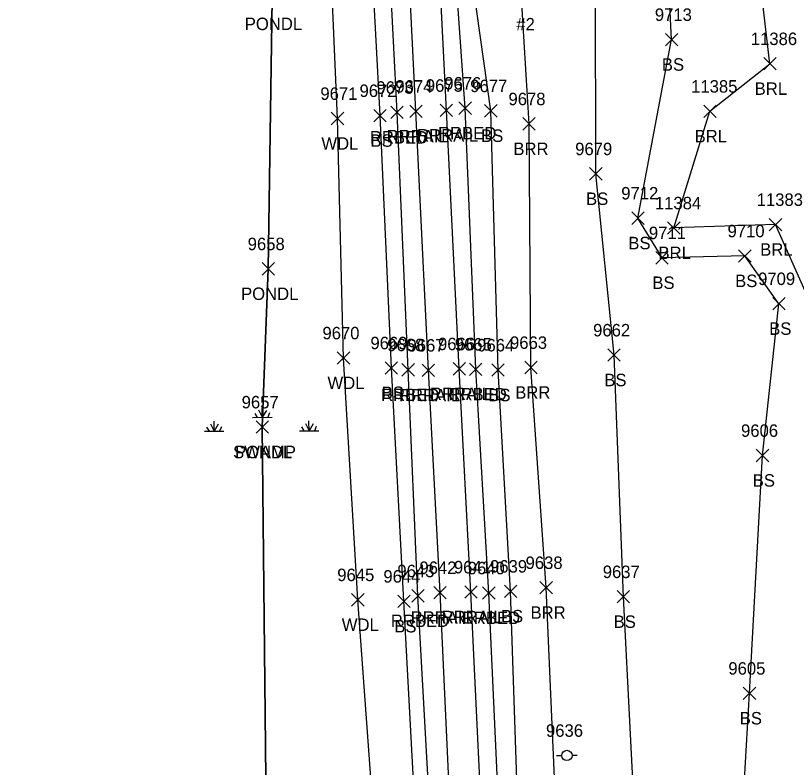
# Model space of a CAD drawing. Extents: x 1769141 to 1770911, y 735471 to 741449.
# Drawn here: x 1770166.6 to 1770292.1, y 739613.2 to 739733.9 of the extents above; entities that cross this region are included whole.
import ezdxf

# ---------------------------------------------------------------- set-up
doc = ezdxf.new("R2010")
doc.units = 0
for name, color, linetype in [('L_A', 7, 'Continuous'), ('L_I', 7, 'Continuous'), ('L_TIC', 7, 'Continuous'), ('LABL', 7, 'Continuous'), ('LAWA', 7, 'Continuous'), ('LAWE', 7, 'Continuous'), ('LELB', 7, 'Continuous'), ('LSOGP', 7, 'Continuous'), ('LWET', 7, 'Continuous'), ('R_A', 7, 'Continuous'), ('R_I', 7, 'Continuous'), ('R_TIC', 7, 'Continuous'), ('RR', 7, 'Continuous'), ('RRB', 7, 'Continuous'), ('U_C', 7, 'Continuous'), ('U_I', 7, 'Continuous'), ('UP', 7, 'Continuous')]:
    doc.layers.add(name, color=color, linetype=linetype)

msp = doc.modelspace()

# ---------------------------------------------------------------- linework, layer by layer
at = {"layer": 'L_TIC'}
for points in [[(1770271.01, 739729.06), (1770273.01, 739731.06)], [(1770273.01, 739729.06), (1770271.01, 739731.06)], [(1770286.82, 739725.18), (1770288.82, 739727.18)], [(1770288.82, 739725.18), (1770286.82, 739727.18)], [(1770241.96, 739717.62), (1770243.96, 739719.62)], [(1770243.96, 739717.62), (1770241.96, 739719.62)], [(1770277.17, 739717.54), (1770279.17, 739719.54)], [(1770279.17, 739717.54), (1770277.17, 739719.54)], [(1770217.32, 739716.38), (1770219.32, 739718.38)], [(1770219.32, 739716.38), (1770217.32, 739718.38)], [(1770224.17, 739716.84), (1770226.17, 739718.84)], [(1770226.17, 739716.84), (1770224.17, 739718.84)], [(1770248.1, 739715.52), (1770250.1, 739717.52)], [(1770250.1, 739715.52), (1770248.1, 739717.52)], [(1770258.83, 739707.5), (1770260.83, 739709.5)], [(1770260.83, 739707.5), (1770258.83, 739709.5)], [(1770265.61, 739700.38), (1770267.61, 739702.38)], [(1770267.61, 739700.38), (1770265.61, 739702.38)], [(1770271.36, 739698.8), (1770273.36, 739700.8)], [(1770273.36, 739698.8), (1770271.36, 739700.8)], [(1770287.7, 739699.35), (1770289.7, 739701.35)], [(1770289.7, 739699.35), (1770287.7, 739701.35)], [(1770269.48, 739694.01), (1770271.48, 739696.01)], [(1770271.48, 739694.01), (1770269.48, 739696.01)], [(1770282.78, 739694.31), (1770284.78, 739696.31)], [(1770284.78, 739694.31), (1770282.78, 739696.31)], [(1770206.21, 739692.24), (1770208.21, 739694.24)], [(1770208.21, 739692.24), (1770206.21, 739694.24)], [(1770288.25, 739686.64), (1770290.25, 739688.64)], [(1770290.25, 739686.64), (1770288.25, 739688.64)], [(1770261.76, 739678.39), (1770263.76, 739680.39)], [(1770263.76, 739678.39), (1770261.76, 739680.39)], [(1770218.3, 739677.92), (1770220.3, 739679.92)], [(1770220.3, 739677.92), (1770218.3, 739679.92)], [(1770225.99, 739676.33), (1770227.99, 739678.33)], [(1770227.99, 739676.33), (1770225.99, 739678.33)], [(1770243.13, 739675.98), (1770245.13, 739677.98)], [(1770245.13, 739675.98), (1770243.13, 739677.98)], [(1770248.41, 739676.39), (1770250.41, 739678.39)], [(1770250.41, 739676.39), (1770248.41, 739678.39)], [(1770205.24, 739666.83), (1770207.24, 739668.83)], [(1770207.24, 739666.83), (1770205.24, 739668.83)], [(1770285.61, 739662.26), (1770287.61, 739664.26)], [(1770287.61, 739662.26), (1770285.61, 739664.26)], [(1770245.15, 739640.46), (1770247.15, 739642.46)], [(1770247.15, 739640.46), (1770245.15, 739642.46)], [(1770250.86, 739641.04), (1770252.86, 739643.04)], [(1770252.86, 739641.04), (1770250.86, 739643.04)], [(1770263.26, 739639.58), (1770265.26, 739641.58)], [(1770265.26, 739639.58), (1770263.26, 739641.58)], [(1770220.6, 739639.09), (1770222.6, 739641.09)], [(1770222.6, 739639.09), (1770220.6, 739641.09)], [(1770228.01, 739638.85), (1770230.01, 739640.85)], [(1770230.01, 739638.85), (1770228.01, 739640.85)], [(1770283.52, 739624.07), (1770285.52, 739626.07)], [(1770285.52, 739624.07), (1770283.52, 739626.07)]]:
    msp.add_lwpolyline(points, dxfattribs=at)
at = {"layer": 'LABL'}
for points in [[(1770280.48, 739010.56), (1770278.67, 739061.29), (1770275.22, 739102.58), (1770273.98, 739143.9), (1770271.83, 739194.56), (1770272.18, 739226.41), (1770266.41, 739273.34), (1770265.32, 739313.93), (1770263.98, 739331.68), (1770262.51, 739367.87), (1770263.52, 739415.26), (1770260.53, 739460.74), (1770259.92, 739511.57), (1770256, 739547.93), (1770251.86, 739642.04), (1770249.41, 739677.39), (1770249.1, 739716.52), (1770247.5, 739742.9), (1770250.29, 739787.04), (1770239.75, 739833.98), (1770250.68, 739842.6), (1770271.28, 739846.58)], [(1770315.73, 739476.29), (1770304.71, 739488.57), (1770301.06, 739512.26), (1770299.15, 739548.11), (1770294.3, 739585.97), (1770295.34, 739626.16), (1770298.21, 739660.91), (1770301.72, 739669.63), (1770297.83, 739679.93), (1770288.7, 739700.35), (1770272.36, 739699.8), (1770278.17, 739718.54), (1770287.82, 739726.18), (1770284.41, 739755.16), (1770271.38, 739789.26), (1770278.23, 739825.22), (1770317.26, 739840.19)]]:
    msp.add_lwpolyline(points, dxfattribs=at)
at = {"layer": 'LAWA'}
msp.add_lwpolyline([(1770252.59, 739004.85), (1770250.18, 739056.62), (1770249.55, 739102.65), (1770247.71, 739141.2), (1770245.33, 739190.56), (1770242.36, 739227.38), (1770239.82, 739271.23), (1770238.25, 739312.92), (1770237.85, 739330.83), (1770235.16, 739366.64), (1770234.45, 739414.73), (1770231.17, 739452.5), (1770229.31, 739510.73), (1770228.41, 739547.1), (1770221.6, 739640.09), (1770219.3, 739678.92), (1770218.32, 739717.38), (1770217.27, 739742.23), (1770215.23, 739783.5), (1770213.34, 739833.64), (1770212.29, 739872.93), (1770209.48, 739912.3), (1770208.36, 739959.05)], dxfattribs=at)
at = {"layer": 'LAWE'}
msp.add_lwpolyline([(1770206.24, 739667.83), (1770207.21, 739693.24), (1770207.81, 739736.58), (1770205.31, 739772.01), (1770201.16, 739812.44), (1770196.11, 739836.01)], dxfattribs=at)
at = {"layer": 'LELB'}
for points in [[(1770260.36, 739007.05), (1770257.15, 739057.78), (1770254.37, 739102.75), (1770254.27, 739140.65), (1770251.63, 739192.93), (1770250.57, 739227.5), (1770245.31, 739271.65), (1770243.46, 739313.07), (1770242.93, 739330.54), (1770243.06, 739367.55), (1770240.84, 739415.54), (1770239.11, 739454.45), (1770236.06, 739510.51), (1770234.02, 739546.38), (1770229.01, 739639.85), (1770226.99, 739677.33), (1770225.17, 739717.84), (1770223.92, 739741.95), (1770222.34, 739783.08), (1770219.19, 739832.99), (1770217.46, 739872.65), (1770215.68, 739912.63), (1770213.23, 739958.7)], [(1770276.81, 739009.84), (1770273.74, 739060.77), (1770271.61, 739103.54), (1770269.74, 739142.6), (1770267.09, 739194.66), (1770265.43, 739227.96), (1770263.03, 739272.74), (1770261.07, 739314.41), (1770259.57, 739330.93), (1770258.94, 739367.52), (1770255.42, 739416.13), (1770253.69, 739456.6), (1770251.03, 739510.78), (1770249.26, 739547.52), (1770246.15, 739641.46), (1770244.13, 739676.98), (1770242.96, 739718.62), (1770239.58, 739742.62), (1770238.3, 739784.58), (1770235.41, 739833.95), (1770233.32, 739872.17), (1770231.41, 739916.36), (1770229.57, 739959.67)], [(1770274.9, 739328.36), (1770274.01, 739362.9), (1770276.03, 739412.1), (1770273.2, 739470.29), (1770269.84, 739512.2), (1770267.17, 739548.12), (1770266.54, 739596.45), (1770264.26, 739640.58), (1770262.76, 739679.39), (1770259.83, 739708.5), (1770259.78, 739739.16), (1770255.12, 739794.4), (1770248.87, 739832.8), (1770253.3, 739830.8), (1770269.97, 739838.36)], [(1770311.39, 739322.25), (1770304.64, 739336.15), (1770303.46, 739365), (1770298.91, 739396.83), (1770299.27, 739435.3), (1770284.41, 739528.87), (1770283.52, 739563.23), (1770282.13, 739583.35), (1770284.52, 739625.07), (1770286.61, 739663.26), (1770289.25, 739687.64), (1770283.78, 739695.31), (1770270.48, 739695.01), (1770266.61, 739701.38), (1770272.01, 739730.06), (1770270.34, 739764.3), (1770262.02, 739792.57), (1770253.3, 739830.8)]]:
    msp.add_lwpolyline(points, dxfattribs=at)
at = {"layer": 'LSOGP'}
msp.add_lwpolyline([(1770166.61, 739945.6), (1770170.77, 739908.19), (1770196.11, 739836.01), (1770201.16, 739812.44), (1770205.31, 739772.01), (1770207.81, 739736.58), (1770207.21, 739693.24), (1770206.24, 739667.83), (1770206.88, 739606.28), (1770193.38, 739597.44), (1770195.63, 739549.88), (1770201.02, 739497.74), (1770201.85, 739468.52)], dxfattribs=at)
at = {"layer": 'LWET'}
for p, q in [((1770205.03, 739670.03), (1770205.42, 739669.39)), ((1770205.64, 739670.58), (1770206.24, 739669.41)), ((1770206.24, 739669.4), (1770206.23, 739670.98)), ((1770206.91, 739670.49), (1770206.24, 739669.41)), ((1770207.4, 739670.09), (1770207.11, 739669.41)), ((1770198.51, 739667.18), (1770198.5, 739668.76)), ((1770204.68, 739669.39), (1770207.81, 739669.41)), ((1770213.75, 739667.23), (1770213.74, 739668.81)), ((1770197.3, 739667.81), (1770197.69, 739667.17)), ((1770197.91, 739668.36), (1770198.52, 739667.18)), ((1770199.18, 739668.27), (1770198.52, 739667.18)), ((1770199.68, 739667.86), (1770199.38, 739667.18)), ((1770206.24, 739667.83), (1770206.24, 739667.83)), ((1770212.55, 739667.87), (1770212.94, 739667.22)), ((1770213.16, 739668.42), (1770213.76, 739667.24)), ((1770214.42, 739668.33), (1770213.76, 739667.24)), ((1770214.92, 739667.92), (1770214.63, 739667.24)), ((1770196.96, 739667.17), (1770200.08, 739667.18)), ((1770198.56, 739667.24), (1770198.52, 739667.24)), ((1770212.2, 739667.22), (1770215.33, 739667.24)), ((1770213.8, 739667.29), (1770213.76, 739667.29))]:
    msp.add_line(p, q, dxfattribs=at)
msp.add_lwpolyline([(1770193.38, 739597.44), (1770206.88, 739606.28), (1770206.24, 739667.83)], dxfattribs=at)
at = {"layer": 'R_TIC'}
for points in [[(1770226.89, 739717.36), (1770228.89, 739719.36)], [(1770228.89, 739717.36), (1770226.89, 739719.36)], [(1770229.94, 739717.54), (1770231.94, 739719.54)], [(1770231.94, 739717.54), (1770229.94, 739719.54)], [(1770234.83, 739717.68), (1770236.83, 739719.68)], [(1770236.83, 739717.68), (1770234.83, 739719.68)], [(1770237.85, 739718.04), (1770239.85, 739720.04)], [(1770239.85, 739718.04), (1770237.85, 739720.04)], [(1770228.68, 739676.02), (1770230.68, 739678.02)], [(1770230.68, 739676.02), (1770228.68, 739678.02)], [(1770231.93, 739675.95), (1770233.93, 739677.95)], [(1770233.93, 739675.95), (1770231.93, 739677.95)], [(1770236.89, 739676.18), (1770238.89, 739678.18)], [(1770238.89, 739676.18), (1770236.89, 739678.18)], [(1770239.53, 739676.11), (1770241.53, 739678.11)], [(1770241.53, 739676.11), (1770239.53, 739678.11)], [(1770230.25, 739639.72), (1770232.25, 739641.72)], [(1770232.25, 739639.72), (1770230.25, 739641.72)], [(1770233.8, 739640.24), (1770235.8, 739642.24)], [(1770235.8, 739640.24), (1770233.8, 739642.24)], [(1770238.77, 739640.33), (1770240.77, 739642.33)], [(1770240.77, 739640.33), (1770238.77, 739642.33)], [(1770241.65, 739640.18), (1770243.65, 739642.18)], [(1770243.65, 739640.18), (1770241.65, 739642.18)]]:
    msp.add_lwpolyline(points, dxfattribs=at)
at = {"layer": 'RR'}
for points in [[(1770265.55, 739008.76), (1770263.29, 739058.54), (1770261.16, 739103.83), (1770259.33, 739141.19), (1770256.65, 739193.93), (1770254.89, 739227.96), (1770252.94, 739271.57), (1770250.86, 739313.64), (1770250.04, 739329.95), (1770248.19, 739367.99), (1770245.87, 739416.26), (1770243.74, 739454.94), (1770241.28, 739510.38), (1770239.17, 739547.11), (1770234.8, 739641.24), (1770232.93, 739676.95), (1770230.94, 739718.54), (1770229.78, 739741.35), (1770227.65, 739783.52), (1770225.28, 739832.75), (1770223.37, 739872.3), (1770221.17, 739914.68), (1770219.13, 739958.93)], [(1770270.62, 739009.24), (1770268.25, 739059.17), (1770266.09, 739103.74), (1770264.05, 739141.88), (1770261.53, 739194.44), (1770259.93, 739228.29), (1770257.89, 739272.24), (1770255.73, 739314.01), (1770254.87, 739330.24), (1770253.06, 739368.17), (1770250.75, 739416.17), (1770248.59, 739454.89), (1770246.14, 739510.65), (1770244.24, 739547.39), (1770239.77, 739641.33), (1770237.89, 739677.18), (1770235.83, 739718.68), (1770234.66, 739742.15), (1770232.59, 739783.92), (1770230.2, 739833.26), (1770228.29, 739872.84), (1770226.13, 739915.51), (1770224.01, 739959.16)]]:
    msp.add_lwpolyline(points, dxfattribs=at)
at = {"layer": 'RRB'}
for points in [[(1770263.31, 739007.85), (1770260.59, 739058.13), (1770258.37, 739103.82), (1770256.72, 739141.21), (1770253.37, 739193.87), (1770252.57, 739227.58), (1770249.5, 739271.45), (1770247.96, 739313.49), (1770246.74, 739330.06), (1770245.36, 739367.64), (1770242.89, 739415.99), (1770240.73, 739454.41), (1770238.1, 739510.32), (1770236.51, 739546.65), (1770231.25, 739640.72), (1770229.68, 739677.02), (1770227.89, 739718.36), (1770226.74, 739741.33), (1770224.83, 739783.26), (1770222.16, 739833.24), (1770220.43, 739872.37), (1770218.06, 739913.92), (1770215.61, 739958.75)], [(1770273.87, 739009.57), (1770271.43, 739060.03), (1770269.42, 739104.03), (1770266.87, 739142.21), (1770264.35, 739194.66), (1770262.74, 739228.17), (1770260.63, 739272.71), (1770258.95, 739314.16), (1770257.8, 739330.85), (1770256.2, 739368.28), (1770253.4, 739415.95), (1770251.19, 739455.1), (1770248.72, 739510.9), (1770246.92, 739547.8), (1770242.65, 739641.18), (1770240.53, 739677.11), (1770238.85, 739719.04), (1770237.16, 739742.59), (1770234.91, 739784.07), (1770232.68, 739833.24), (1770230.96, 739872.77), (1770228.86, 739915.81), (1770226.33, 739959.11)]]:
    msp.add_lwpolyline(points, dxfattribs=at)
at = {"layer": 'UP'}
for p, q in [((1770253.53, 739615.09), (1770254.36, 739615.09)), ((1770255.19, 739615.09), (1770255.19, 739615.09)), ((1770256.86, 739615.09), (1770256.02, 739615.09)), ((1770256.02, 739615.09), (1770256.02, 739615.09)), ((1770256.86, 739615.09), (1770256.86, 739615.09))]:
    msp.add_line(p, q, dxfattribs=at)
msp.add_circle((1770255.19, 739615.09), 0.833, dxfattribs=at)

# ---------------------------------------------------------------- texts
at = {"layer": 'L_A'}
for s, p in [('PONDL', (1770203.43, 739731.58)), ('BS', (1770270.45, 739725.06)), ('BRL', (1770285.36, 739721.18)), ('BS', (1770241.4, 739713.62)), ('BRL', (1770275.71, 739713.54)), ('WDL', (1770215.74, 739712.38)), ('BS', (1770223.62, 739712.84)), ('BRR', (1770246.59, 739711.52)), ('BS', (1770258.27, 739703.5)), ('BS', (1770265.06, 739696.38)), ('BRL', (1770269.9, 739694.8)), ('BRL', (1770286.25, 739695.35)), ('BS', (1770268.92, 739690.01)), ('BS', (1770282.22, 739690.31)), ('PONDL', (1770202.83, 739688.24)), ('BS', (1770287.69, 739682.64)), ('BS', (1770261.2, 739674.39)), ('WDL', (1770216.72, 739673.92)), ('BS', (1770225.43, 739672.33)), ('BS', (1770242.57, 739671.98)), ('BRR', (1770246.89, 739672.39)), ('SWAMP', (1770201.55, 739662.83)), ('PONDL', (1770201.86, 739662.83)), ('BS', (1770285.05, 739658.26)), ('BRR', (1770249.35, 739637.04)), ('BS', (1770244.59, 739636.46)), ('BS', (1770262.7, 739635.58)), ('WDL', (1770219.02, 739635.09)), ('BS', (1770227.45, 739634.85)), ('BS', (1770282.96, 739620.07))]:
    msp.add_text(s, height=2, dxfattribs=at).set_placement(p)
at = {"layer": 'L_I'}
for s, p in [('9713', (1770269.32, 739733.06)), ('11386', (1770284.74, 739729.18)), ('9672', (1770221.87, 739720.84)), ('9677', (1770239.66, 739721.62)), ('11385', (1770275.15, 739721.54)), ('9671', (1770215.58, 739720.38)), ('9678', (1770245.8, 739719.52)), ('9679', (1770256.52, 739711.5)), ('9712', (1770263.92, 739704.38)), ('11383', (1770285.68, 739703.35)), ('11384', (1770269.33, 739702.8)), ('9710', (1770281, 739698.31)), ('9711', (1770268.36, 739698.01)), ('9658', (1770203.9, 739696.24)), ('9709', (1770285.91, 739690.64)), ('9670', (1770215.91, 739681.92)), ('9662', (1770259.4, 739682.39)), ('9669', (1770223.62, 739680.33)), ('9664', (1770240.78, 739679.98)), ('9663', (1770246.05, 739680.39)), ('9657', (1770202.93, 739670.83)), ('9657', (1770202.93, 739670.83)), ('9606', (1770283.17, 739666.26)), ('9639', (1770242.84, 739644.46)), ('9638', (1770248.55, 739645.04)), ('9645', (1770218.29, 739643.09)), ('9637', (1770260.95, 739643.58)), ('9644', (1770225.7, 739642.85)), ('9605', (1770281.13, 739628.07))]:
    msp.add_text(s, height=2, dxfattribs=at).set_placement(p)
at = {"layer": 'R_A'}
for s, p in [('RRBED', (1770223.53, 739713.36)), ('RRRAIL', (1770226.23, 739713.54)), ('RRRAIL', (1770231.12, 739713.68)), ('RRBED', (1770234.49, 739714.04)), ('RRBED', (1770225.33, 739672.02)), ('RRRAIL', (1770228.22, 739671.95)), ('RRRAIL', (1770233.18, 739672.18)), ('RRBED', (1770236.17, 739672.11)), ('RRBED', (1770226.9, 739635.72)), ('RRRAIL', (1770230.09, 739636.24)), ('RRRAIL', (1770235.06, 739636.33)), ('RRBED', (1770238.3, 739636.18))]:
    msp.add_text(s, height=2, dxfattribs=at).set_placement(p)
at = {"layer": 'R_I'}
for s, p in [('9676', (1770235.48, 739722.04)), ('9673', (1770224.58, 739721.36)), ('9674', (1770227.63, 739721.54)), ('9675', (1770232.52, 739721.68)), ('9668', (1770226.33, 739680.02)), ('9667', (1770229.58, 739679.95)), ('9666', (1770234.48, 739680.18)), ('9665', (1770237.17, 739680.11)), ('9642', (1770231.49, 739644.24)), ('9641', (1770237.03, 739644.33)), ('9640', (1770239.26, 739644.18)), ('9643', (1770227.95, 739643.72))]:
    msp.add_text(s, height=2, dxfattribs=at).set_placement(p)
at = {"layer": 'U_C'}
msp.add_text('#2', height=2, dxfattribs=at).set_placement((1770247.06, 739731.53))
at = {"layer": 'U_I'}
msp.add_text('9636', height=2, dxfattribs=at).set_placement((1770251.83, 739618.09))

doc.saveas('drawing.dxf')
